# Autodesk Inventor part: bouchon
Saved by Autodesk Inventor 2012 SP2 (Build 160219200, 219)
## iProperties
Created: 2013-04
Part Number: bouchon
Material: Default
Document SubType Name: Modeling
Designer: papa
Density: 1 g/cm^3
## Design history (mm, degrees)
node "bouchon1"
node "bouchon"
node "Base1"
